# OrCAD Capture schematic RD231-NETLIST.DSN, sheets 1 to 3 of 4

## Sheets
1 4: size A3
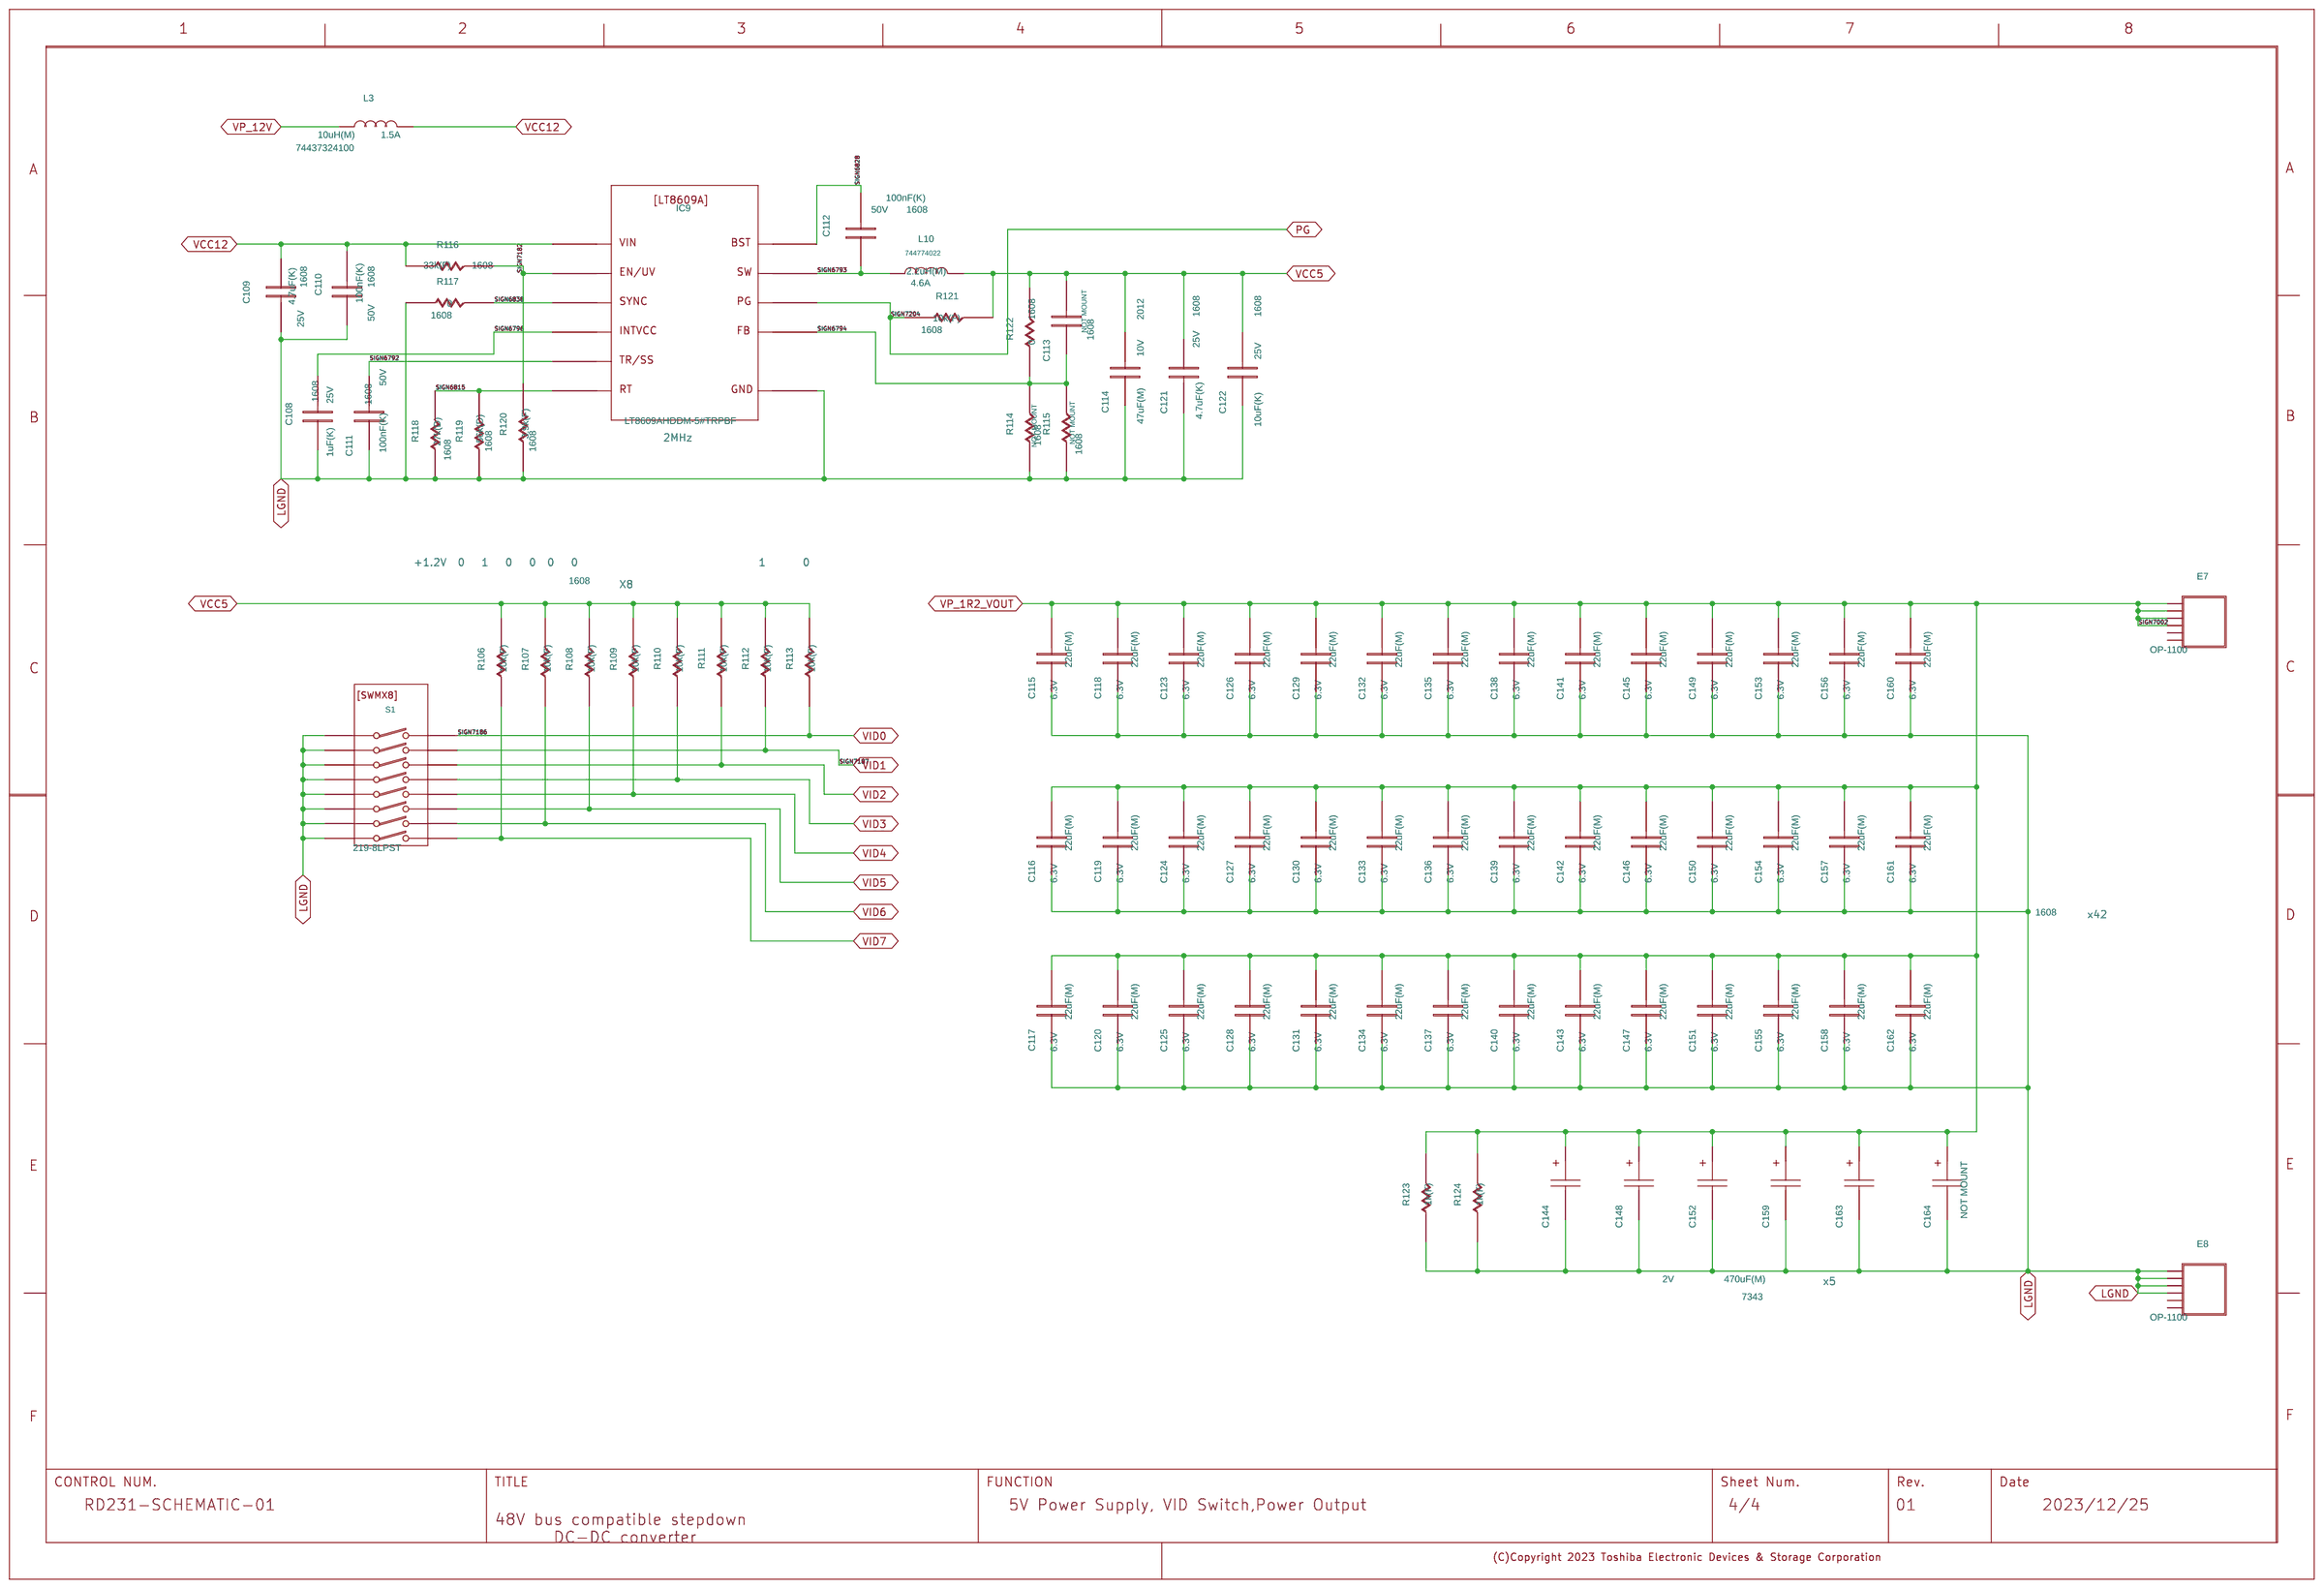
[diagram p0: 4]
2 3: size A3
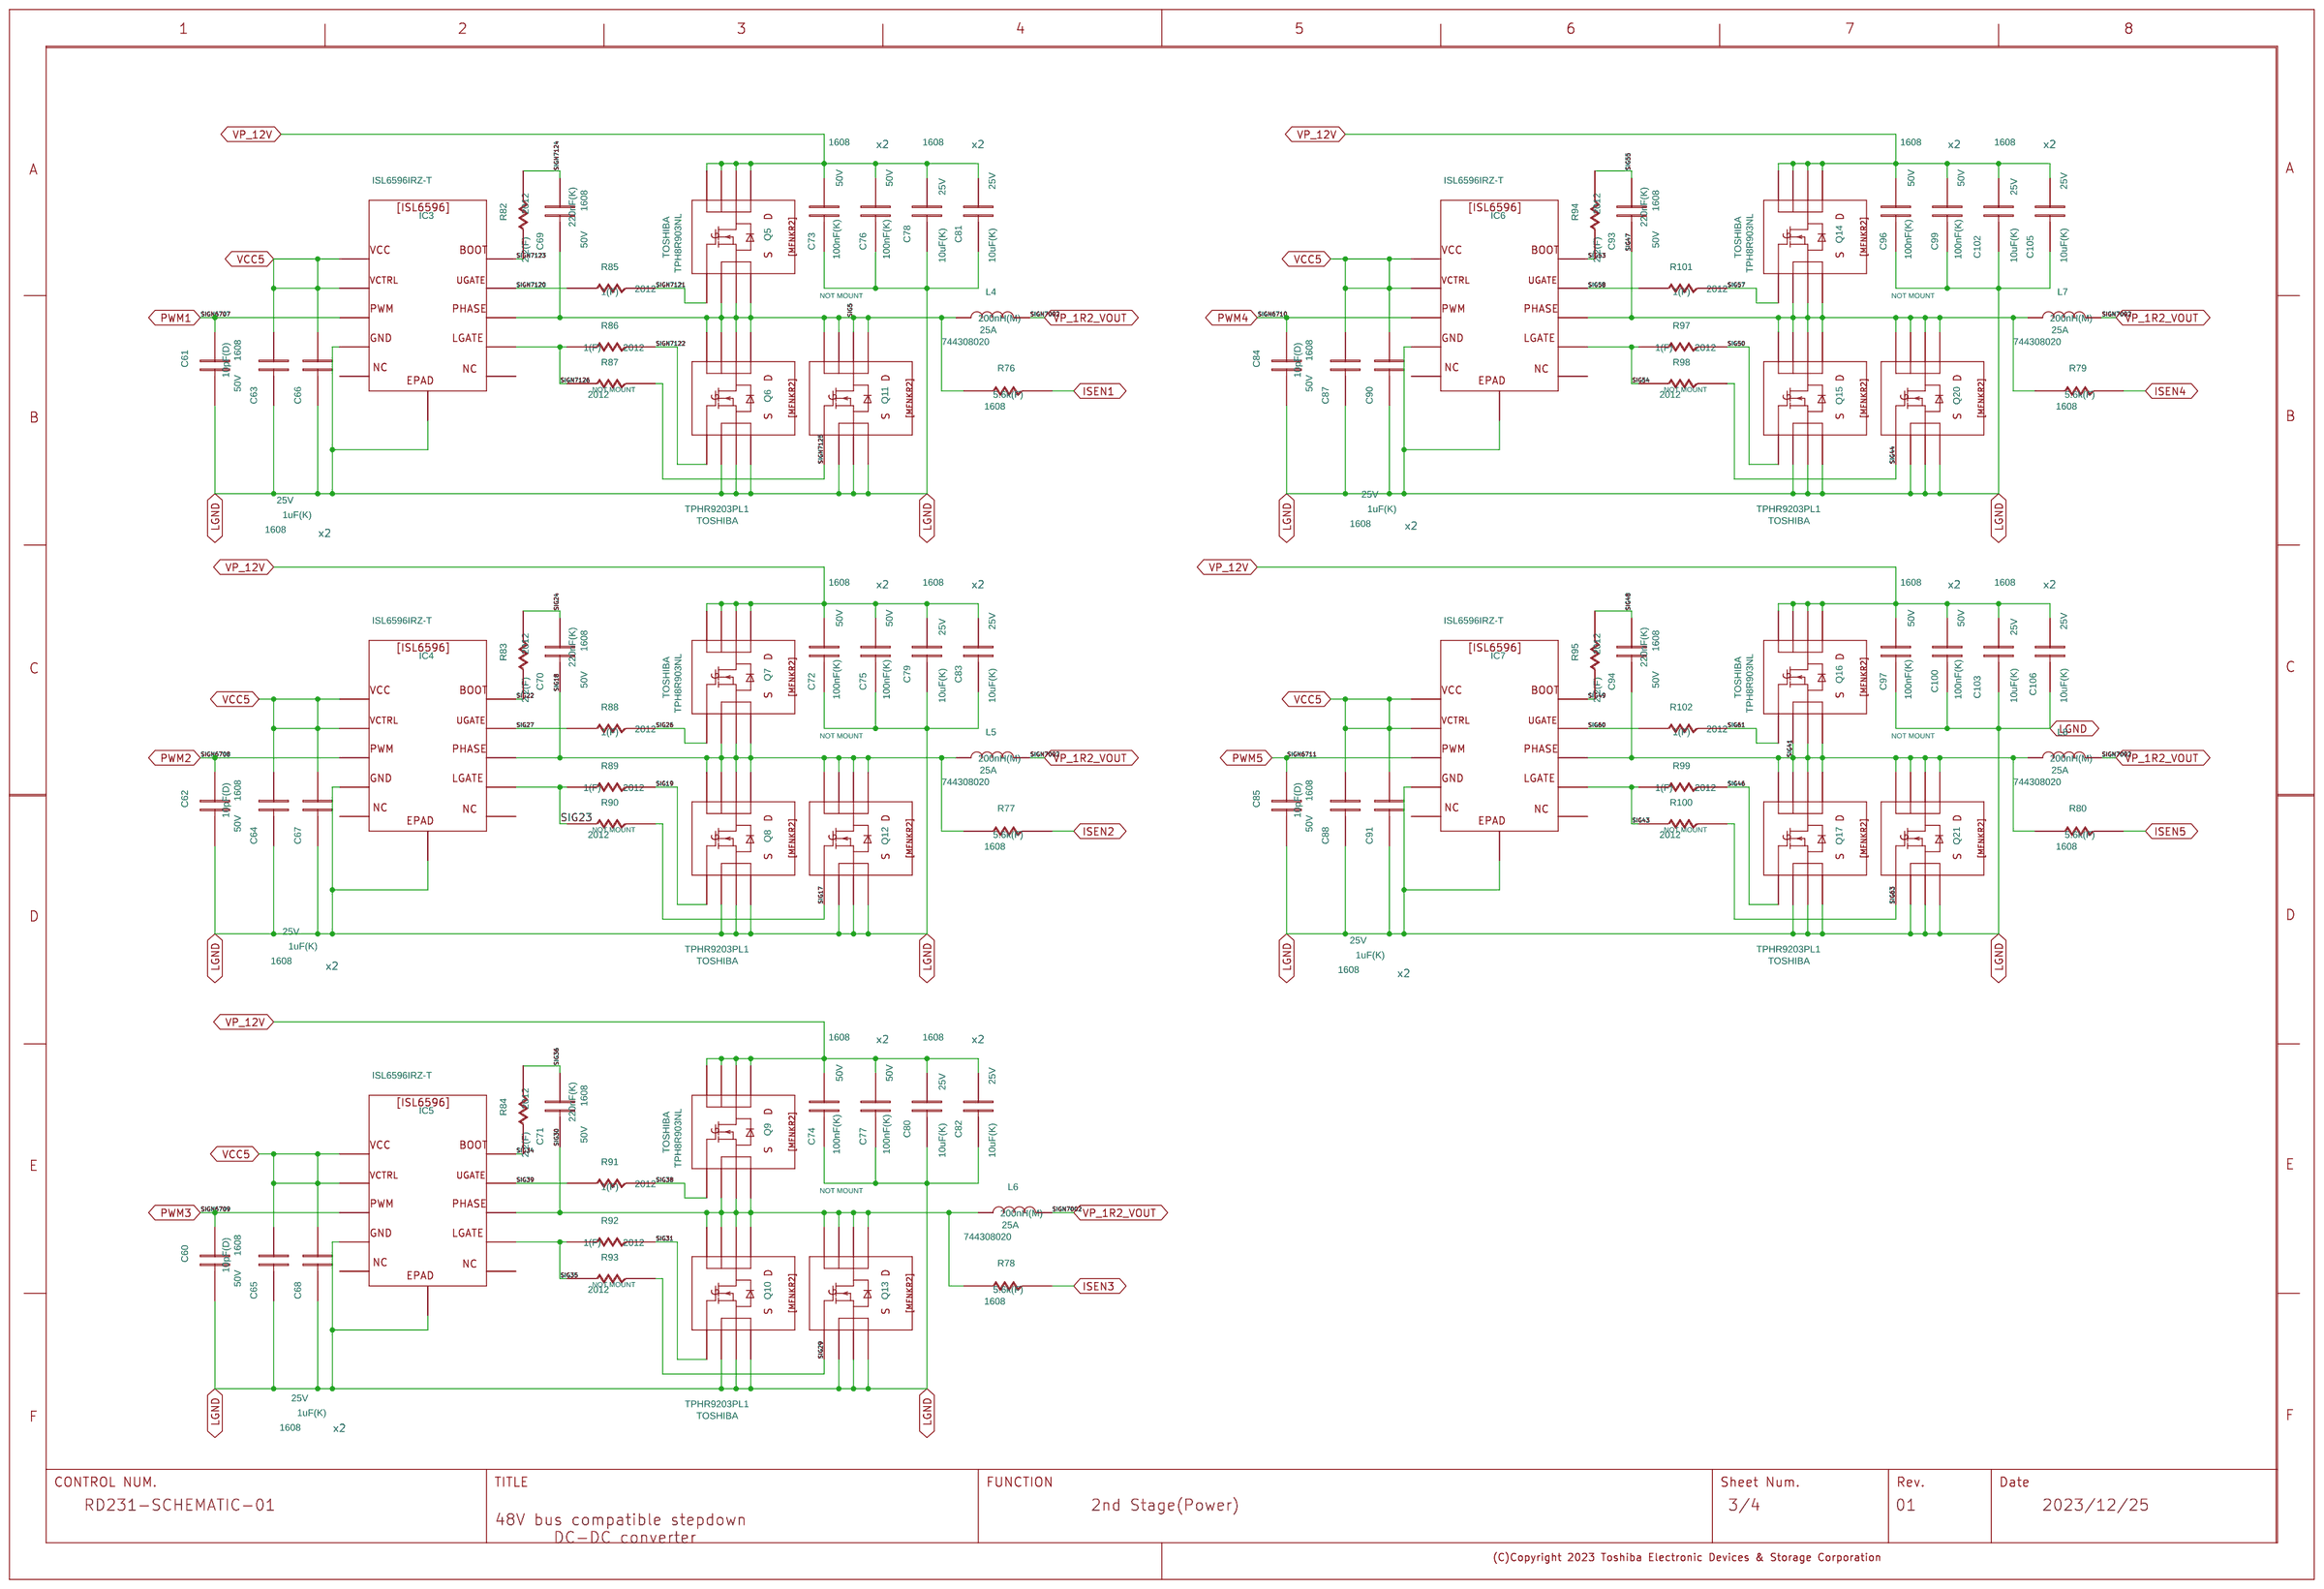
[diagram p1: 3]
3 2: size A3
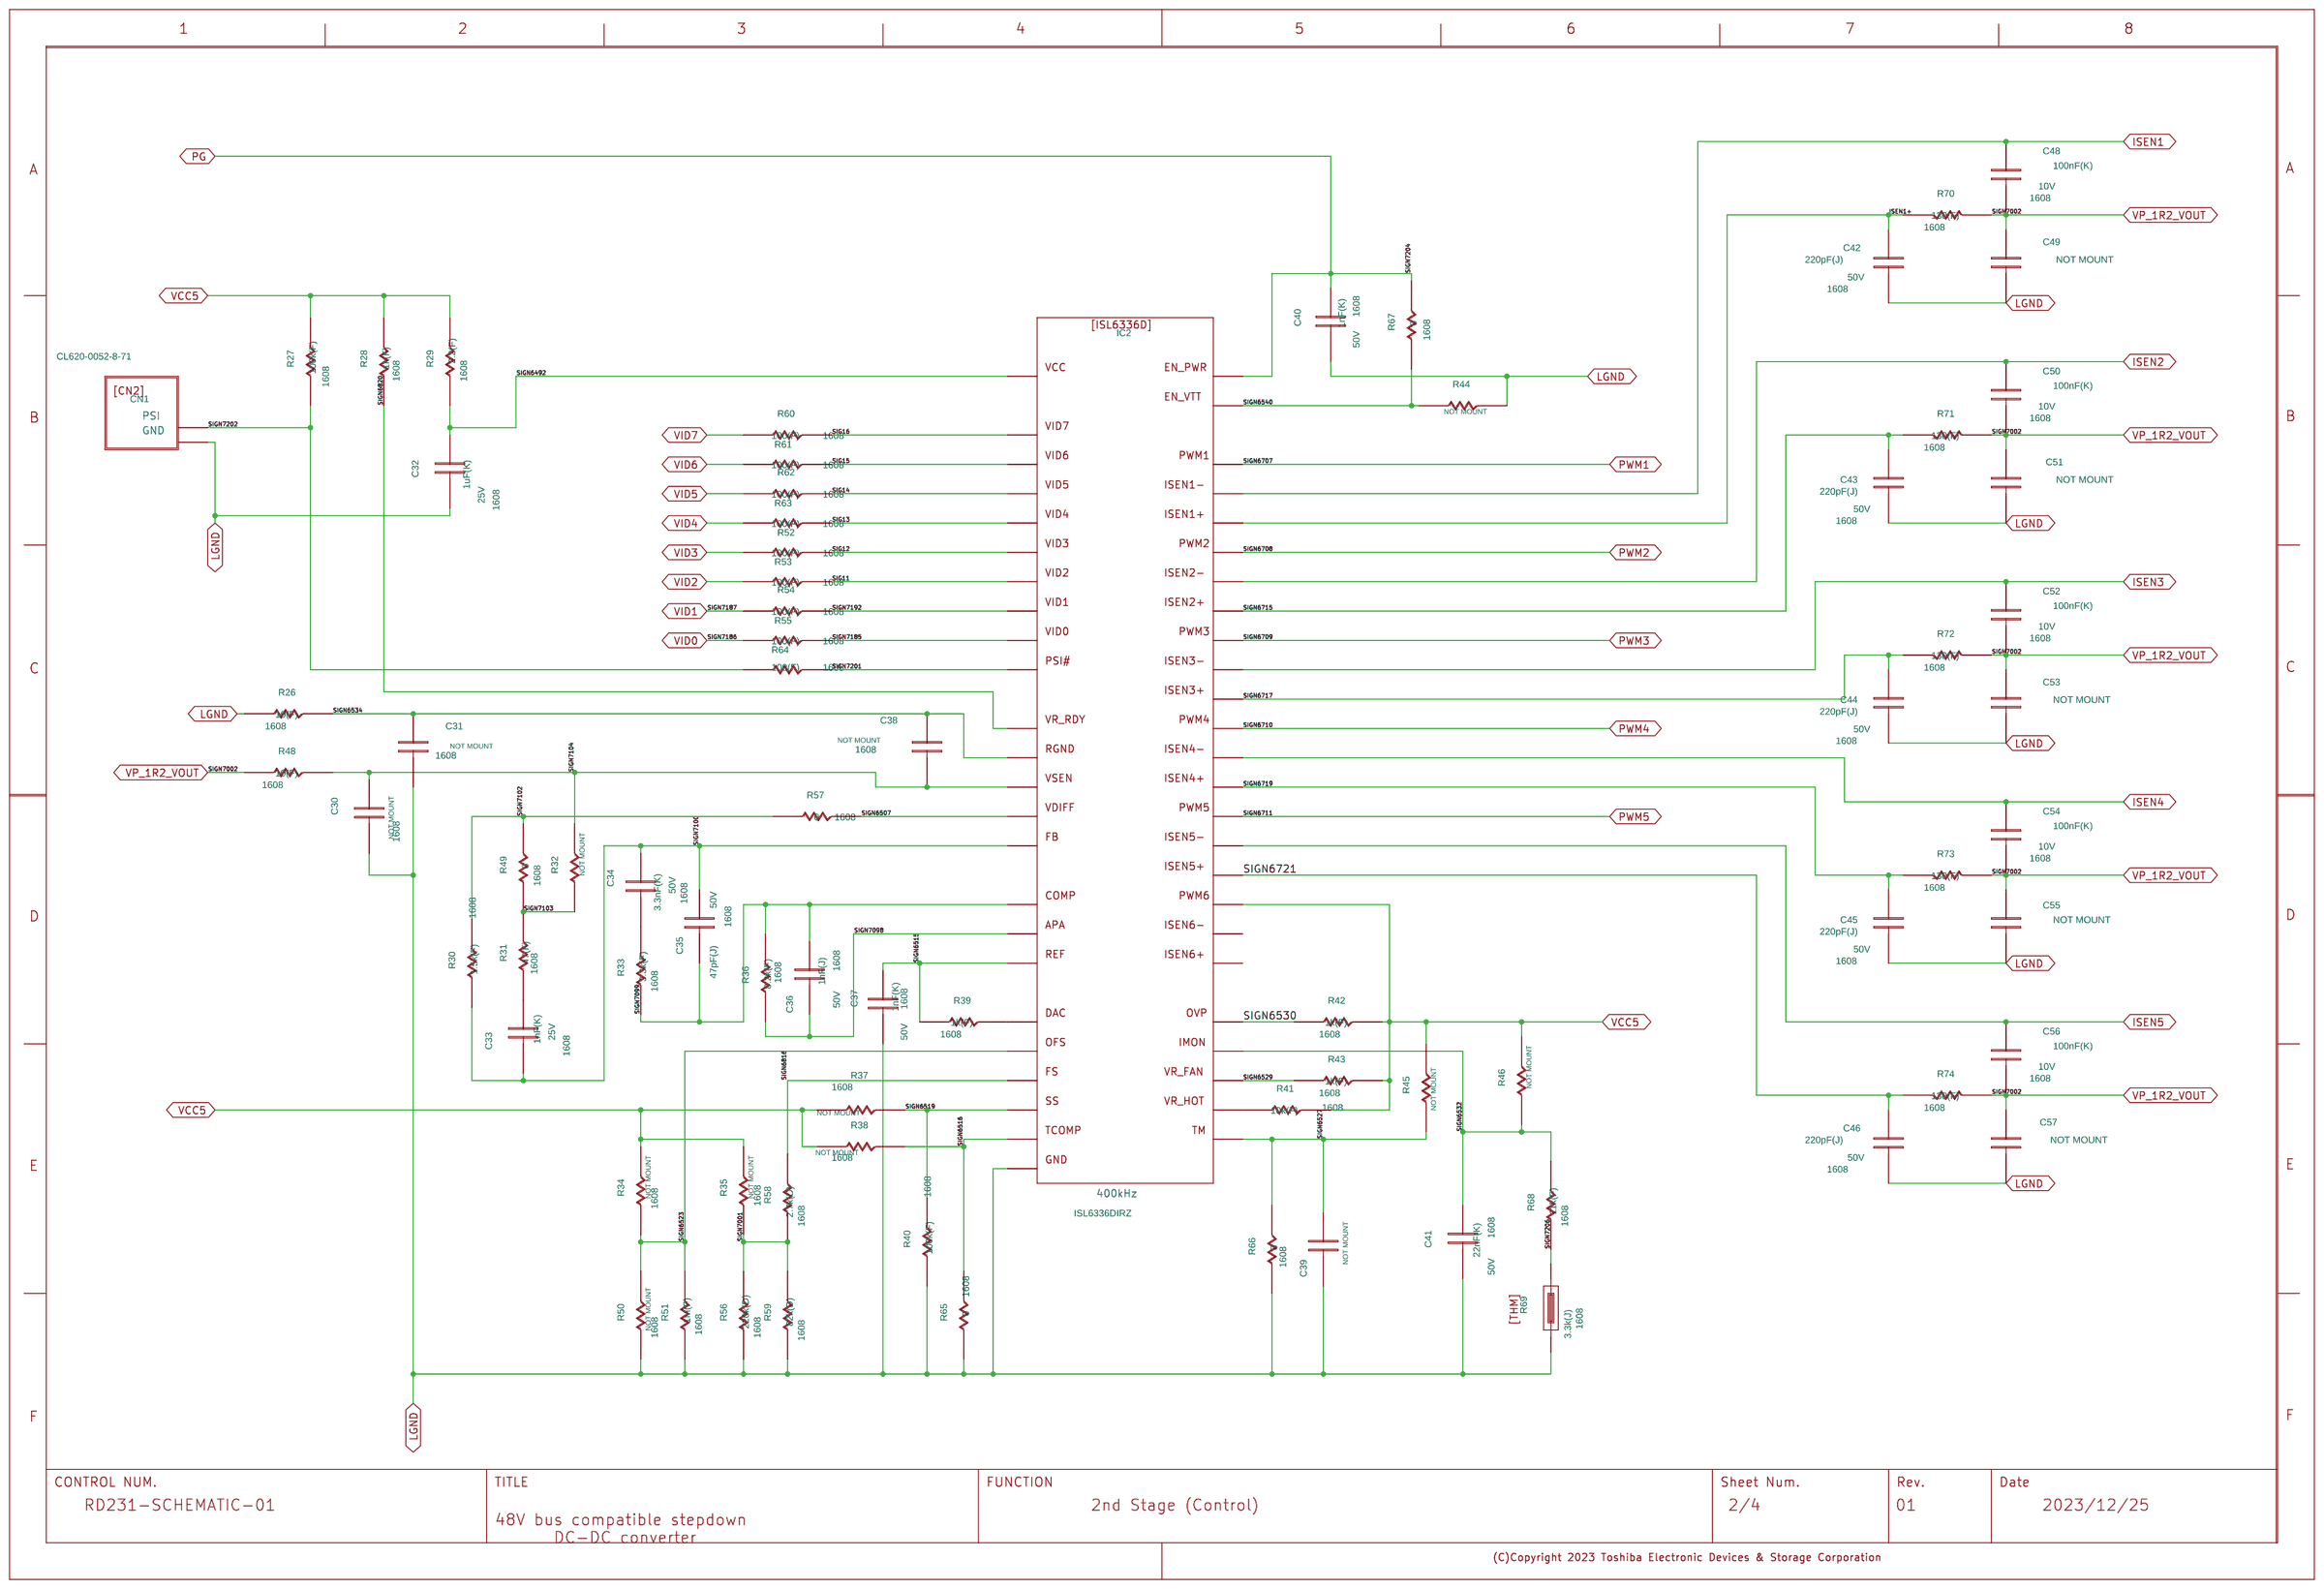
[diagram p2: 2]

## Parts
sheet 2
C30  C
C31  C
C32  C
C33  C
C34  C
C35  C
C36  C
C37  C
C38  C
C39  C
C40  C
C41  C
C42  C
C43  C
C44  C
C45  C
C46  C
C48  C
C49  C
C50  C
C51  C
C52  C
C53  C
C54  C
C55  C
C56  C
C57  C
CN1  CN2
IC2  ISL6336D
R26  R
R27  R
R28  R
R29  R
R30  R
R31  R
R32  R
R33  R
R34  R
R35  R
R36  R
R37  R
R38  R
R39  R
R40  R
R41  R
R42  R
R43  R
R44  R
R45  R
R46  R
R48  R
R49  R
R50  R
R51  R
R52  R
R53  R
R54  R
R55  R
R56  R
R57  R
R58  R
R59  R
R60  R
R61  R
R62  R
R63  R
R64  R
R65  R
R66  R
R67  R
R68  R
R69  THM
R70  R
R71  R
R72  R
R73  R
R74  R
U?#2  WAKU_DEF100
sheet 3
C60  C
C61  C
C62  C
C63  C
C64  C
C65  C
C66  C
C67  C
C68  C
C69  C
C70  C
C71  C
C72  C
C73  C
C74  C
C75  C
C76  C
C77  C
C78  C
C79  C
C80  C
C81  C
C82  C
C83  C
C84  C
C85  C
C87  C
C88  C
C90  C
C91  C
C93  C
C94  C
C96  C
C97  C
C99  C
C100  C
C102  C
C103  C
C105  C
C106  C
IC3  ISL6596
IC4  ISL6596
IC5  ISL6596
IC6  ISL6596
IC7  ISL6596
L4  L
L5  L
L6  L
L7  L
L8  L
Q5  MFNKR2
Q6  MFNKR2
Q7  MFNKR2
Q8  MFNKR2
Q9  MFNKR2
Q10  MFNKR2
Q11  MFNKR2
Q12  MFNKR2
Q13  MFNKR2
Q14  MFNKR2
Q15  MFNKR2
Q16  MFNKR2
Q17  MFNKR2
Q20  MFNKR2
Q21  MFNKR2
R76  R
R77  R
R78  R
R79  R
R80  R
R82  R
R83  R
R84  R
R85  R
R86  R
R87  R
R88  R
R89  R
R90  R
R91  R
R92  R
R93  R
R94  R
R95  R
R97  R
R98  R
R99  R
R100  R
R101  R
R102  R
U?#1  WAKU_DEF100
sheet 4
C108  C
C109  C
C110  C
C111  C
C112  C
C113  C
C114  C
C115  C
C116  C
C117  C
C118  C
C119  C
C120  C
C121  C
C122  C
C123  C
C124  C
C125  C
C126  C
C127  C
C128  C
C129  C
C130  C
C131  C
C132  C
C133  C
C134  C
C135  C
C136  C
C137  C
C138  C
C139  C
C140  C
C141  C
C142  C
C143  C
C144  CP
C145  C
C146  C
C147  C
C148  CP
C149  C
C150  C
C151  C
C152  CP
C153  C
C154  C
C155  C
C156  C
C157  C
C158  C
C159  CP
C160  C
C161  C
C162  C
C163  CP
C164  CP
E7  EB1
E8  EB1
IC9  LT8609A
L3  L
L10  L
R106  R
R107  R
R108  R
R109  R
R110  R
R111  R
R112  R
R113  R
R114  R
R115  R
R116  R
R117  R
R118  R
R119  R
R120  R
R121  R
R122  R
R123  R
R124  R
S1  SWMX8
U?#4  WAKU_DEF100

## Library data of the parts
C30 C31 C38 C39 = C: COMP: G36030011310; COMPONENTNAME: G36030011310_package; COMPONENTTYPE: 4; FNCLASSCODEG: P03-03; FNPARTSNAMEG: CHIP CERAMIC CAPACITOR (1608); FUNCN: G36030011310; GCOUNT: 1; MAXGCOUNT: 1; MFFORMINGDIVP: KC; MFMOUNTSYMBOLP: 80; MFPACKAGEMETHOP: S; MFSOLDERINGPROP: .; NOTMOUNT: NOT MOUNT; PCODE: P03039AAN526; SIZECODESMD: 1608; TOLERANCE: K; USEINPARTSLIST: YES; USEWITHLAYOUT: YES; USEWITHSCHEMA: YES
C32 C63-C68 C87 C88 C90 C91 C108 = C: COMP: G36030011433; COMPONENTNAME: G36030011433_package; COMPONENTTYPE: 4; FNCLASSCODEG: P03-03; FNPARTSNAMEG: CHIP CERAMIC CAPACITOR (1608); FUNCN: G36030011433; GCOUNT: 1; MAXGCOUNT: 1; MFFORMINGDIVP: KC; MFMOUNTSYMBOLP: 80; MFPACKAGEMETHOP: S; MFSOLDERINGPROP: .; PCODE: P03039992230; SIZECODESMD: 1608; USEINPARTSLIST: YES; USEWITHLAYOUT: YES; USEWITHSCHEMA: YES; VAL1: 1uF(K); VAL2: 25V
C33 = C: COMP: G36030011297; COMPONENTNAME: G36030011297_package; COMPONENTTYPE: 4; FNCLASSCODEG: P03-03; FNPARTSNAMEG: CHIP CERAMIC CAPACITOR (1608); FUNCN: G36030011297; GCOUNT: 1; MAXGCOUNT: 1; MFFORMINGDIVP: KC; MFMOUNTSYMBOLP: 80; MFPACKAGEMETHOP: S; MFSOLDERINGPROP: .; PCODE: P03039008221; SIZECODESMD: 1608; TOLERANCE: K; USEINPARTSLIST: YES; USEWITHLAYOUT: YES; USEWITHSCHEMA: YES; VAL1: 1nF(K); VAL2: 25V
C34 = C: COMP: G36030011037; COMPONENTNAME: G36030011037_package; COMPONENTTYPE: 4; FNCLASSCODEG: P03-03; FNPARTSNAMEG: CHIP CERAMIC CAPACITOR (1608); FUNCN: G36030011037; GCOUNT: 1; MAXGCOUNT: 1; MFFORMINGDIVP: KC; MFMOUNTSYMBOLP: 80; MFPACKAGEMETHOP: S; MFSOLDERINGPROP: .; PCODE: P03039A0T125; SIZECODESMD: 1608; TOLERANCE: K; USEINPARTSLIST: YES; USEWITHLAYOUT: YES; USEWITHSCHEMA: YES; VAL1: 3.3nF(K); VAL2: 50V
C35 = C: COMP: G36030011303; COMPONENTNAME: G36030011303_package; COMPONENTTYPE: 4; FNCLASSCODEG: P03-03; FNPARTSNAMEG: CHIP CERAMIC CAPACITOR (1608); FUNCN: G36030011303; GCOUNT: 1; MAXGCOUNT: 1; MFFORMINGDIVP: KC; MFMOUNTSYMBOLP: 80; MFPACKAGEMETHOP: S; MFSOLDERINGPROP: .; PCODE: P03039A0P127; SIZECODESMD: 1608; TOLERANCE: K; USEINPARTSLIST: YES; USEWITHLAYOUT: YES; USEWITHSCHEMA: YES; VAL1: 47pF(J); VAL2: 50V
C36 = C: COMP: G36030011747; COMPONENTNAME: G36030011747_package; COMPONENTTYPE: 4; FNCLASSCODEG: P03-03; FNPARTSNAMEG: CHIP CERAMIC CAPACITOR (1608); FUNCN: G36030011747; GCOUNT: 1; MAXGCOUNT: 1; MFFORMINGDIVP: KC; MFMOUNTSYMBOLP: 80; MFPACKAGEMETHOP: S; MFSOLDERINGPROP: .; PCODE: P03190012112; SIZECODESMD: 1608; USEINPARTSLIST: YES; USEWITHLAYOUT: YES; USEWITHSCHEMA: YES; VAL1: 1nF(J); VAL2: 50V
C37 C40 = C: COMP: G36030011044; COMPONENTNAME: G36030011044_package; COMPONENTTYPE: 4; FNCLASSCODEG: P03-03; FNPARTSNAMEG: CHIP CERAMIC CAPACITOR (1608); FUNCN: G36030011044; GCOUNT: 1; MAXGCOUNT: 1; MFFORMINGDIVP: KC; MFMOUNTSYMBOLP: 80; MFPACKAGEMETHOP: S; MFSOLDERINGPROP: .; PCODE: P03039045226; SIZECODESMD: 1608; TOLERANCE: K; USEINPARTSLIST: YES; USEWITHLAYOUT: YES; USEWITHSCHEMA: YES; VAL1: 1nF(K); VAL2: 50V
C41 = C: COMP: G36030011297; COMPONENTNAME: G36030011297_package; COMPONENTTYPE: 4; FNCLASSCODEG: P03-03; FNPARTSNAMEG: CHIP CERAMIC CAPACITOR (1608); FUNCN: G36030011297; GCOUNT: 1; MAXGCOUNT: 1; MFFORMINGDIVP: KC; MFMOUNTSYMBOLP: 80; MFPACKAGEMETHOP: S; MFSOLDERINGPROP: .; PCODE: P03039008221; SIZECODESMD: 1608; TOLERANCE: K; USEINPARTSLIST: YES; USEWITHLAYOUT: YES; USEWITHSCHEMA: YES; VAL1: 22nF(K); VAL2: 50V
C42-C46 = C: COMP: G36030011488; COMPONENTNAME: G36030011488_package; COMPONENTTYPE: 4; FNCLASSCODEG: P03-03; FNPARTSNAMEG: CHIP CERAMIC CAPACITOR (1608); FUNCN: G36030011488; GCOUNT: 1; MAXGCOUNT: 1; MFFORMINGDIVP: KC; MFMOUNTSYMBOLP: 80; MFPACKAGEMETHOP: S; MFSOLDERINGPROP: .; PCODE: P03039269127; SIZECODESMD: 1608; USEINPARTSLIST: YES; USEWITHLAYOUT: YES; USEWITHSCHEMA: YES; VAL1: 220pF(J); VAL2: 50V
C48 C50 C52 C54 C56 = C: COMP: GDM030000714; COMPONENTNAME: GDM030000714_package; COMPONENTTYPE: 4; FNCLASSCODEG: P03-03; FNPARTSNAMEG: CHIP CERAMIC CAPACITOR (1608); FUNCN: GDM030000714; GCOUNT: 1; MAXGCOUNT: 1; MFFORMINGDIVP: KC; MFMOUNTSYMBOLP: 80; MFPACKAGEMETHOP: S; MFSOLDERINGPROP: .; PCODE: P03039ABE123; SIZECODESMD: 1608; USEINPARTSLIST: YES; USEWITHLAYOUT: YES; USEWITHSCHEMA: YES; VAL1: 100nF(K); VAL2: 10V
C49 C51 C53 C55 C57 = C: COMP: G36030104128; COMPONENTNAME: G36030104128_package; COMPONENTTYPE: 4; FNCLASSCODEG: P03-03; FNPARTSNAMEG: CHIP CERAMIC CAPACITOR (1608); FUNCN: G36030104128; GCOUNT: 1; MAXGCOUNT: 1; MFFORMINGDIVP: KC; MFMOUNTSYMBOLP: 80; MFPACKAGEMETHOP: S; MFSOLDERINGPROP: .; NOTMOUNT: NOT MOUNT; PCODE: P03039ABG127; SIZECODESMD: 1608; USEINPARTSLIST: YES; USEWITHLAYOUT: YES; USEWITHSCHEMA: YES
CN1 = CN2: COMP: ZS_DPJ028; COMPONENTNAME: ZS_DPJ028_package; COMPONENTTYPE: 4; FUNCN: ZS_DPJ028; GCOUNT: 1; MAXGCOUNT: 1; OUMEPARTTYPE: PJ; QUADMODEL: dummymodel; USEINPARTSLIST: YES; USEWITHLAYOUT: YES; USEWITHSCHEMA: YES; VAL1: CL620-0052-8-71; VAL3: CL620-0052-8-71
IC2 = ISL6336D: COMP: ISL6336DIRZ; COMPONENTNAME: ISL6336D.ISL6336D; COMPONENTTYPE: 4; GCOUNT: 1; MAXGCOUNT: 1; OUMEMAKER: Renesas; OUMEMAKERKATAMEI: ISL6336DIRZ; USEINPARTSLIST: YES; USEWITHLAYOUT: YES; USEWITHSCHEMA: YES; VAL1: ISL6336DIRZ; VAL3: ISL6336DIRZ
R26 = R: COMP: G36010104063; COMPONENTNAME: G36010104063_package; COMPONENTTYPE: 4; FNCLASSCODEG: P01-08; FNPARTSNAMEG: CHIP RESISTOR (1608); FUNCN: G36010104063; MFFORMINGDIVP: KC; MFMOUNTSYMBOLP: 80; MFPACKAGEMETHOP: S; MFSOLDERINGPROP: .; NUMBEROFELEMENT: 0; PCODE: P01042036620; SIZECODESMD: 1608; TOLERANCE: F; USEINPARTSLIST: YES; USEWITHLAYOUT: YES; USEWITHSCHEMA: YES; VAL1: 10(F); VAL2: 100mW
R27 R40 = R: COMP: G36010027133; COMPONENTNAME: G36010027133_package; COMPONENTTYPE: 4; FNCLASSCODEG: P01-08; FNPARTSNAMEG: CHIP RESISTOR (1608); FUNCN: G36010027133; MFFORMINGDIVP: KC; MFMOUNTSYMBOLP: 80; MFPACKAGEMETHOP: S; MFSOLDERINGPROP: .; NUMBEROFELEMENT: 0; PCODE: P01042045226; SIZECODESMD: 1608; TOLERANCE: F; USEINPARTSLIST: YES; USEWITHLAYOUT: YES; USEWITHSCHEMA: YES; VAL1: 100k(F); VAL2: 100mW
R28 R123 R124 = R: COMP: G36010027324; COMPONENTNAME: G36010027324_package; COMPONENTTYPE: 4; FNCLASSCODEG: P01-08; FNPARTSNAMEG: CHIP RESISTOR (1608); FUNCN: G36010027324; GCOUNT: 1; MAXGCOUNT: 1; MFFORMINGDIVP: KC; MFMOUNTSYMBOLP: 80; MFPACKAGEMETHOP: S; MFSOLDERINGPROP: .; NUMBEROFELEMENT: 0; PCODE: P01042521225; SIZECODESMD: 1608; TOLERANCE: F; USEINPARTSLIST: YES; USEWITHLAYOUT: YES; USEWITHSCHEMA: YES; VAL1: 1k(F); VAL2: 100mW
R29 = R: COMP: G36010141013; COMPONENTNAME: G36010141013_package; COMPONENTTYPE: 4; FNCLASSCODEG: P01-08; FNPARTSNAMEG: CHIP RESISTOR (1608); FUNCN: G36010141013; MFFORMINGDIVP: KC; MFMOUNTSYMBOLP: 80; MFPACKAGEMETHOP: S; MFSOLDERINGPROP: .; NUMBEROFELEMENT: 0; PCODE: P01183001112; SIZECODESMD: 1608; USEINPARTSLIST: YES; USEWITHLAYOUT: YES; USEWITHSCHEMA: YES; VAL1: 2.2(F); VAL2: 100mW
R30 = R: COMP: G36010104339; COMPONENTNAME: G36010104339_package; COMPONENTTYPE: 4; FNCLASSCODEG: P01-08; FNPARTSNAMEG: CHIP RESISTOR (1608); FUNCN: G36010104339; MFFORMINGDIVP: KC; MFMOUNTSYMBOLP: 80; MFPACKAGEMETHOP: S; MFSOLDERINGPROP: .; NUMBEROFELEMENT: 0; PCODE: P01042159428; SIZECODESMD: 1608; USEINPARTSLIST: YES; USEWITHLAYOUT: YES; USEWITHSCHEMA: YES; VAL1: 1.5k(F); VAL2: 100mW
R31 = R: COMP: K0100346; COMPONENTNAME: K0100346_package; COMPONENTTYPE: 4; FNCLASSCODEG: P01-08; FNPARTSNAMEG: CHIP JUMPER 1608TYPE; FUNCN: K0100346; GCOUNT: 1; MAXGCOUNT: 1; PARTCOMMENT: ã\Z<KC0008> ªtbgvgÉo^³êÄ¢Ü¹ñB; SIZECODESMD: 1608; USEINPARTSLIST: YES; USEWITHLAYOUT: YES; USEWITHSCHEMA: YES; VAL1: 47(F); VAL2: 100mW
R32 R34 R35 R37 R44 = R: COMP: G36010129400; COMPONENTNAME: G36010129400_package; COMPONENTTYPE: 4; FNCLASSCODEG: P01-08; FNPARTSNAMEG: CHIP RESISTOR (1608); FUNCN: G36010129400; MFFORMINGDIVP: KC; MFMOUNTSYMBOLP: 80; MFPACKAGEMETHOP: S; MFSOLDERINGPROP: .; NOTMOUNT: NOT MOUNT; NUMBEROFELEMENT: 0; PCODE: P01117044116; SIZECODESMD: 1608; USEINPARTSLIST: YES; USEWITHLAYOUT: YES; USEWITHSCHEMA: YES
R33 = R: COMP: G36010104353; COMPONENTNAME: G36010104353_package; COMPONENTTYPE: 4; FNCLASSCODEG: P01-08; FNPARTSNAMEG: CHIP RESISTOR (1608); FUNCN: G36010104353; GCOUNT: 1; MAXGCOUNT: 1; MFFORMINGDIVP: KC; MFMOUNTSYMBOLP: 80; MFPACKAGEMETHOP: S; MFSOLDERINGPROP: .; NUMBEROFELEMENT: 0; PCODE: P01042007620; SIZECODESMD: 1608; USEINPARTSLIST: YES; USEWITHLAYOUT: YES; USEWITHSCHEMA: YES; VAL1: 3.3k(F); VAL2: 100mW
R36 = R: COMP: G36010027188; COMPONENTNAME: G36010027188_package; COMPONENTTYPE: 4; FNCLASSCODEG: P01-08; FNPARTSNAMEG: CHIP RESISTOR (1608); FUNCN: G36010027188; MFFORMINGDIVP: KC; MFMOUNTSYMBOLP: 80; MFPACKAGEMETHOP: S; MFSOLDERINGPROP: .; NUMBEROFELEMENT: 0; PCODE: P01042507328; SIZECODESMD: 1608; TOLERANCE: F; USEINPARTSLIST: YES; USEWITHLAYOUT: YES; USEWITHSCHEMA: YES; VAL1: 8.2k(F); VAL2: 100mW
R38 = R: COMP: G36010027034; COMPONENTNAME: G36010027034_package; COMPONENTTYPE: 4; FNCLASSCODEG: P01-08; FNPARTSNAMEG: CHIP RESISTOR (1608); FUNCN: G36010027034; MFFORMINGDIVP: KC; MFMOUNTSYMBOLP: 80; MFPACKAGEMETHOP: S; MFSOLDERINGPROP: .; NOTMOUNT: NOT MOUNT; NUMBEROFELEMENT: 0; PCODE: P01042049A26; SIZECODESMD: 1608; TOLERANCE: F; USEINPARTSLIST: YES; USEWITHLAYOUT: YES; USEWITHSCHEMA: YES
R39 R42 R43 = R: COMP: G36010027324; COMPONENTNAME: G36010027324_package; COMPONENTTYPE: 4; FNCLASSCODEG: P01-08; FNPARTSNAMEG: CHIP RESISTOR (1608); FUNCN: G36010027324; MFFORMINGDIVP: KC; MFMOUNTSYMBOLP: 80; MFPACKAGEMETHOP: S; MFSOLDERINGPROP: .; NUMBEROFELEMENT: 0; PCODE: P01042521225; SIZECODESMD: 1608; TOLERANCE: F; USEINPARTSLIST: YES; USEWITHLAYOUT: YES; USEWITHSCHEMA: YES; VAL1: 1k(F); VAL2: 100mW
R41 R106-R113 = R: COMP: G36010027034; COMPONENTNAME: G36010027034_package; COMPONENTTYPE: 4; FNCLASSCODEG: P01-08; FNPARTSNAMEG: CHIP RESISTOR (1608); FUNCN: G36010027034; MFFORMINGDIVP: KC; MFMOUNTSYMBOLP: 80; MFPACKAGEMETHOP: S; MFSOLDERINGPROP: .; NUMBEROFELEMENT: 0; PCODE: P01042049A26; SIZECODESMD: 1608; TOLERANCE: F; USEINPARTSLIST: YES; USEWITHLAYOUT: YES; USEWITHSCHEMA: YES; VAL1: 10k(F); VAL2: 100mW
R45 = R: COMP: G36010027324; COMPONENTNAME: G36010027324_package; COMPONENTTYPE: 4; FNCLASSCODEG: P01-08; FNPARTSNAMEG: CHIP RESISTOR (1608); FUNCN: G36010027324; MFFORMINGDIVP: KC; MFMOUNTSYMBOLP: 80; MFPACKAGEMETHOP: S; MFSOLDERINGPROP: .; NOTMOUNT: NOT MOUNT; NUMBEROFELEMENT: 0; PCODE: P01042521225; SIZECODESMD: 1608; TOLERANCE: F; USEINPARTSLIST: YES; USEWITHLAYOUT: YES; USEWITHSCHEMA: YES
R46 = R: COMP: G5101106E109; COMPONENTNAME: G5101106E109_package; COMPONENTTYPE: 4; FNCLASSCODEG: P01-08; FNPARTSNAMEG: CHIP RESISTOR (1608); FUNCN: G5101106E109; MFFORMINGDIVP: KC; MFMOUNTSYMBOLP: 80; MFPACKAGEMETHOP: S; MFSOLDERINGPROP: .; NOTMOUNT: NOT MOUNT; NUMBEROFELEMENT: 0; PCODE: P01042153228; SIZECODESMD: 1608; USEINPARTSLIST: YES; USEWITHLAYOUT: YES; USEWITHSCHEMA: YES
R48 = R: COMP: G36010104063; COMPONENTNAME: G36010104063_package; COMPONENTTYPE: 4; FNCLASSCODEG: P01-08; FNPARTSNAMEG: CHIP RESISTOR (1608); FUNCN: G36010104063; GCOUNT: 1; MAXGCOUNT: 1; MFFORMINGDIVP: KC; MFMOUNTSYMBOLP: 80; MFPACKAGEMETHOP: S; MFSOLDERINGPROP: .; NUMBEROFELEMENT: 0; PCODE: P01042036620; SIZECODESMD: 1608; TOLERANCE: F; USEINPARTSLIST: YES; USEWITHLAYOUT: YES; USEWITHSCHEMA: YES; VAL1: 10(F); VAL2: 100mW
R49 R57 R65-R67 R117 R122 = R: COMP: K0100346; COMPONENTNAME: K0100346_package; COMPONENTTYPE: 4; FNCLASSCODEG: P01-08; FNPARTSNAMEG: CHIP JUMPER 1608TYPE; FUNCN: K0100346; GCOUNT: 1; MAXGCOUNT: 1; PARTCOMMENT: ã\Z<KC0008> ªtbgvgÉo^³êÄ¢Ü¹ñB; SIZECODESMD: 1608; USEINPARTSLIST: YES; USEWITHLAYOUT: YES; USEWITHSCHEMA: YES; VAL1: 0
R50 = R: COMP: G36010129639; COMPONENTNAME: G36010129639_package; COMPONENTTYPE: 4; FNCLASSCODEG: P01-08; FNPARTSNAMEG: CHIP RESISTOR (1608); FUNCN: G36010129639; GCOUNT: 1; MAXGCOUNT: 1; MFFORMINGDIVP: KC; MFMOUNTSYMBOLP: 80; MFPACKAGEMETHOP: S; MFSOLDERINGPROP: .; NOTMOUNT: NOT MOUNT; NUMBEROFELEMENT: 0; PCODE: P01117067115; SIZECODESMD: 1608; USEINPARTSLIST: YES; USEWITHLAYOUT: YES; USEWITHSCHEMA: YES
R51 = R: COMP: G5101106E109; COMPONENTNAME: G5101106E109_package; COMPONENTTYPE: 4; FNCLASSCODEG: P01-08; FNPARTSNAMEG: CHIP RESISTOR (1608); FUNCN: G5101106E109; GCOUNT: 1; MAXGCOUNT: 1; MFFORMINGDIVP: KC; MFMOUNTSYMBOLP: 80; MFPACKAGEMETHOP: S; MFSOLDERINGPROP: .; NUMBEROFELEMENT: 0; PCODE: P01042153228; SIZECODESMD: 1608; USEINPARTSLIST: YES; USEWITHLAYOUT: YES; USEWITHSCHEMA: YES; VAL1: 1M(F); VAL2: 100mW
R52-R55 R60-R64 = R: COMP: G36010104087; COMPONENTNAME: G36010104087_package; COMPONENTTYPE: 4; FNCLASSCODEG: P01-08; FNPARTSNAMEG: CHIP RESISTOR (1608); FUNCN: G36010104087; GCOUNT: 1; MAXGCOUNT: 1; MFFORMINGDIVP: KC; MFMOUNTSYMBOLP: 80; MFPACKAGEMETHOP: S; MFSOLDERINGPROP: .; NUMBEROFELEMENT: 0; PCODE: P01042041426; SIZECODESMD: 1608; TOLERANCE: F; USEINPARTSLIST: YES; USEWITHLAYOUT: YES; USEWITHSCHEMA: YES; VAL1: 100(F); VAL2: 100mW
R56 = R: COMP: G36010014355; COMPONENTNAME: G36010014355_package; COMPONENTTYPE: 4; FNCLASSCODEG: P01-08; FNPARTSNAMEG: CHIP RESISTOR (1608); FUNCN: G36010014355; GCOUNT: 1; MAXGCOUNT: 1; MFFORMINGDIVP: KC; MFMOUNTSYMBOLP: 80; MFPACKAGEMETHOP: S; MFSOLDERINGPROP: .; NUMBEROFELEMENT: 0; PCODE: P01042201820; SIZECODESMD: 1608; USEINPARTSLIST: YES; USEWITHLAYOUT: YES; USEWITHSCHEMA: YES; VAL1: 220k(D); VAL2: 62.5mW
R58 = R: COMP: G36010129356; COMPONENTNAME: G36010129356_package; COMPONENTTYPE: 4; FNCLASSCODEG: P01-08; FNPARTSNAMEG: CHIP RESISTOR (1608); FUNCN: G36010129356; GCOUNT: 1; MAXGCOUNT: 1; MFFORMINGDIVP: KC; MFMOUNTSYMBOLP: 80; MFPACKAGEMETHOP: S; MFSOLDERINGPROP: .; NUMBEROFELEMENT: 0; PCODE: P01117039112; SIZECODESMD: 1608; USEINPARTSLIST: YES; USEWITHLAYOUT: YES; USEWITHSCHEMA: YES; VAL1: 2.7k(D); VAL2: 62.5mW
R59 = R: COMP: G36010129714; COMPONENTNAME: G36010129714_package; COMPONENTTYPE: 4; FNCLASSCODEG: P01-08; FNPARTSNAMEG: CHIP RESISTOR (1608); FUNCN: G36010129714; GCOUNT: 1; MAXGCOUNT: 1; MFFORMINGDIVP: KC; MFMOUNTSYMBOLP: 80; MFPACKAGEMETHOP: S; MFSOLDERINGPROP: .; NUMBEROFELEMENT: 0; PCODE: P01117075110; SIZECODESMD: 1608; USEINPARTSLIST: YES; USEWITHLAYOUT: YES; USEWITHSCHEMA: YES; VAL1: 82k(D); VAL2: 62.5mW
R68 = R: COMP: G36010027164; COMPONENTNAME: G36010027164_package; COMPONENTTYPE: 4; FNCLASSCODEG: P01-08; FNPARTSNAMEG: CHIP RESISTOR (1608); FUNCN: G36010027164; GCOUNT: 1; MAXGCOUNT: 1; MFFORMINGDIVP: KC; MFMOUNTSYMBOLP: 80; MFPACKAGEMETHOP: S; MFSOLDERINGPROP: .; NUMBEROFELEMENT: 0; PCODE: P01042066221; SIZECODESMD: 1608; TOLERANCE: F; USEINPARTSLIST: YES; USEWITHLAYOUT: YES; USEWITHSCHEMA: YES; VAL1: 11k(F); VAL2: 100mW
R69 = THM: COMP: K0900027; COMPONENTKIND: 105; COMPONENTNAME: K0900027_package; COMPONENTTYPE: 4; DCSPARKOVERVOLT: 0.000000000000000; FNCLASSCODEG: P09-01; FNPARTSCODEG: MT; FNPARTSNAMEG: CHIP NTC THERMISTOR; FUNCN: K0900027; GCOUNT: 1; MAXGCOUNT: 1; MFFORMINGDIVP: KC; MFMOUNTSYMBOLP: 80; MFPACKAGEMETHOP: S; MFSOLDERINGPROP: .; OUMEPARTTYPE: MT; PARTCOMMENT: ã\Z<KC0008> ªtbgvgÉo^³êÄ¢Ü¹ñB; SIZECODESMD: 1608; USEINPARTSLIST: YES; USEWITHLAYOUT: YES; USEWITHSCHEMA: YES; VAL1: 3.3k(J); VAL2: 100mW; VARISTORVOLTAGE: 0
R70-R74 = R: COMP: G5101104N107; COMPONENTNAME: G5101104N107_package; COMPONENTTYPE: 4; FNCLASSCODEG: P01-08; FNPARTSNAMEG: CHIP RESISTOR (1608); FUNCN: G5101104N107; GCOUNT: 1; MAXGCOUNT: 1; MFFORMINGDIVP: KC; MFMOUNTSYMBOLP: 80; MFPACKAGEMETHOP: S; MFSOLDERINGPROP: .; NUMBEROFELEMENT: 0; PCODE: P01042089220; SIZECODESMD: 1608; USEINPARTSLIST: YES; USEWITHLAYOUT: YES; USEWITHSCHEMA: YES; VAL1: 130(F); VAL2: 100mW
U?#2 = WAKU_DEF100: AUTHOR: d9000436; COMPONENTTYPE: 2; DATE: 2023/12/25; DRAWINGNUMBER: RD231-SCHEMATIC-01; FUNCTION: 2nd Stage (Control); REVISION: 01; SAVEAREA0: -56280,0,471144,298016; SHEETNUMBER: 2/4; TIME: 20:22:11; TITLE: 48V bus compatible stepdown / DC-DC converter; UPDATEDATE: 2024/01/12; UPDATETIME: 11:35:27; UPDATEUSER: sptcae13
C60-C62 C84 C85 = C: COMP: G36030011013; COMPONENTNAME: G36030011013_package; COMPONENTTYPE: 4; FNCLASSCODEG: P03-03; FNPARTSNAMEG: CHIP CERAMIC CAPACITOR (1608); FUNCN: G36030011013; GCOUNT: 1; MAXGCOUNT: 1; MFFORMINGDIVP: KC; MFMOUNTSYMBOLP: 80; MFPACKAGEMETHOP: S; MFSOLDERINGPROP: .; PCODE: P03039185229; SIZECODESMD: 1608; TOLERANCE: D; USEINPARTSLIST: YES; USEWITHLAYOUT: YES; USEWITHSCHEMA: YES; VAL1: 10pF(D); VAL2: 50V
C69-C71 C93 C94 = C: COMP: G36030104104; COMPONENTNAME: G36030104104_package; COMPONENTTYPE: 4; FNCLASSCODEG: P03-03; FNPARTSNAMEG: CHIP CERAMIC CAPACITOR (1608); FUNCN: G36030104104; GCOUNT: 1; MAXGCOUNT: 1; MFFORMINGDIVP: KC; MFMOUNTSYMBOLP: 80; MFPACKAGEMETHOP: S; MFSOLDERINGPROP: .; PCODE: P03039ABE123; SIZECODESMD: 1608; USEINPARTSLIST: YES; USEWITHLAYOUT: YES; USEWITHSCHEMA: YES; VAL1: 220nF(K); VAL2: 50V
C72-C77 C96 C97 C99 C100 = C: COMP: G36030011419; COMPONENTNAME: G36030011419_package; COMPONENTTYPE: 4; FNCLASSCODEG: P03-03; FNPARTSNAMEG: CHIP CERAMIC CAPACITOR (1608); FUNCN: G36030011419; GCOUNT: 1; MAXGCOUNT: 1; MFFORMINGDIVP: KC; MFMOUNTSYMBOLP: 80; MFPACKAGEMETHOP: S; MFSOLDERINGPROP: .; PCODE: P03039996139; SIZECODESMD: 1608; USEINPARTSLIST: YES; USEWITHLAYOUT: YES; USEWITHSCHEMA: YES; VAL1: 100nF(K); VAL2: 50V
C78-C83 C102 C103 C105 C106 = C: COMP: G36030011433; COMPONENTNAME: G36030011433_package; COMPONENTTYPE: 4; FNCLASSCODEG: P03-03; FNPARTSNAMEG: CHIP CERAMIC CAPACITOR (1608); FUNCN: G36030011433; GCOUNT: 1; MAXGCOUNT: 1; MFFORMINGDIVP: KC; MFMOUNTSYMBOLP: 80; MFPACKAGEMETHOP: S; MFSOLDERINGPROP: .; PCODE: P03039992230; SIZECODESMD: 1608; USEINPARTSLIST: YES; USEWITHLAYOUT: YES; USEWITHSCHEMA: YES; VAL1: 10uF(K); VAL2: 25V
IC3-IC7 = ISL6596: COMP: G36470287016; COMPONENTTYPE: 4; VAL1: ISL6596IRZ-T; VAL3: ISL6596IRZ-T
L4-L8 = L: COMP: 7443082022; COMPONENTNAME: pinass:L_func:L; COMPONENTTYPE: 8; GCOUNT: 1; MAXGCOUNT: 1; OUMEMAKER: Wurth; OUMEMAKERKATAMEI: 7443082022; USEINPARTSLIST: YES; USEWITHLAYOUT: YES; USEWITHSCHEMA: YES; VAL1: 200nH(M); VAL2: 25A; VAL3: 744308020
Q5 Q7 Q9 Q14 Q16 = MFNKR2: COMP: TPH6R003NL; COMPONENTNAME: MFNKR2_MFNKR2; COMPONENTTYPE: 4; GCOUNT: 1; MAXGCOUNT: 1; OUMEMAKER: TOSHIBA; OUMEMAKERKATAMEI: TPH6R003NL; USEINPARTSLIST: YES; USERCOMPTEXT3: TOSHIBA; USEWITHLAYOUT: YES; USEWITHSCHEMA: YES; VAL1: TPH8R903NL; VAL3: TPH8R903NL
Q6 Q8 Q10 Q15 Q17 = MFNKR2: COMP: TPH6R003NL; COMPONENTNAME: MFNKR2_MFNKR2; COMPONENTTYPE: 4; GCOUNT: 1; MAXGCOUNT: 1; OUMEMAKER: TOSHIBA; OUMEMAKERKATAMEI: TPH6R003NL; USEINPARTSLIST: YES; USERCOMPTEXT3: TOSHIBA; USEWITHLAYOUT: YES; USEWITHSCHEMA: YES; VAL1: TPHR9203PL1; VAL3: TPHR9203PL1
Q11-Q13 Q20 Q21 = MFNKR2: COMP: TPH6R003NL; COMPONENTNAME: MFNKR2_MFNKR2; COMPONENTTYPE: 4; GCOUNT: 1; MAXGCOUNT: 1; NOTMOUNT: NOT MOUNT; OUMEMAKER: TOSHIBA; OUMEMAKERKATAMEI: TPH6R003NL; USEINPARTSLIST: YES; USEWITHLAYOUT: YES; USEWITHSCHEMA: YES
R76-R80 = R: COMPONENTTYPE: 4; SIZECODESMD: 1608; VAL1: 5.6k(F); VAL2: 62.5mW
R82-R84 R94 R95 = R: COMP: G36010106012; COMPONENTNAME: G36010106012_package; COMPONENTTYPE: 4; FNCLASSCODEG: P01-08; FNPARTSNAMEG: CHIP RESISTOR (2012); FUNCN: G36010106012; GCOUNT: 1; MAXGCOUNT: 1; MFFORMINGDIVP: KC; MFMOUNTSYMBOLP: 90; MFPACKAGEMETHOP: S; MFSOLDERINGPROP: .; NUMBEROFELEMENT: 0; PCODE: P01048019214; SIZECODESMD: 2012; USEINPARTSLIST: YES; USEWITHLAYOUT: YES; USEWITHSCHEMA: YES; VAL1: 2.2(F); VAL2: 125mW
R85 R86 R88 R89 R91 R92 R97 R99 R101 R102 = R: COMP: G36010106081; COMPONENTNAME: G36010106081_package; COMPONENTTYPE: 4; FNCLASSCODEG: P01-08; FNPARTSNAMEG: CHIP RESISTOR (2012); FUNCN: G36010106081; GCOUNT: 1; MAXGCOUNT: 1; MFFORMINGDIVP: KC; MFMOUNTSYMBOLP: 90; MFPACKAGEMETHOP: S; MFSOLDERINGPROP: .; NUMBEROFELEMENT: 0; PCODE: P01048017210; SIZECODESMD: 2012; USEINPARTSLIST: YES; USEWITHLAYOUT: YES; USEWITHSCHEMA: YES; VAL1: 1(F); VAL2: 125mW
R87 R90 R93 R98 R100 = R: COMP: G36010106081; COMPONENTNAME: G36010106081_package; COMPONENTTYPE: 4; FNCLASSCODEG: P01-08; FNPARTSNAMEG: CHIP RESISTOR (2012); FUNCN: G36010106081; GCOUNT: 1; MAXGCOUNT: 1; MFFORMINGDIVP: KC; MFMOUNTSYMBOLP: 90; MFPACKAGEMETHOP: S; MFSOLDERINGPROP: .; NOTMOUNT: NOT MOUNT; NUMBEROFELEMENT: 0; PCODE: P01048017210; SIZECODESMD: 2012; USEINPARTSLIST: YES; USEWITHLAYOUT: YES; USEWITHSCHEMA: YES
U?#1 = WAKU_DEF100: AUTHOR: osozawa; COMPONENTTYPE: 2; DATE: 2023/12/25; DRAWINGNUMBER: RD231-SCHEMATIC-01; FUNCTION: 2nd Stage(Power); REVISION: 01; SAVEAREA0: 315434,-7824,400773,39368; SHEETNUMBER: 3/4; TIME: 14:26:19; TITLE: 48V bus compatible stepdown / DC-DC converter; UPDATEDATE: 2024/01/12; UPDATETIME: 11:36:35; UPDATEUSER: sptcae13
C109 = C: COMP: GDM030000053; COMPONENTNAME: GDM030000053_package; COMPONENTTYPE: 4; FNCLASSCODEG: P03-03; FNPARTSNAMEG: CHIP CERAMIC CAPACITOR (1608); FUNCN: GDM030000053; GCOUNT: 1; MAXGCOUNT: 1; MFFORMINGDIVP: KC; MFMOUNTSYMBOLP: 80; MFPACKAGEMETHOP: S; MFSOLDERINGPROP: .; PCODE: P03B000000MS; SIZECODESMD: 1608; USEINPARTSLIST: YES; USEWITHLAYOUT: YES; USEWITHSCHEMA: YES; VAL1: 4.7uF(K); VAL2: 25V
C110 C112 = C: COMP: G36030104036; COMPONENTNAME: G36030104036_package; COMPONENTTYPE: 4; FNCLASSCODEG: P03-03; FNPARTSNAMEG: CHIP CERAMIC CAPACITOR (1608); FUNCN: G36030104036; GCOUNT: 1; MAXGCOUNT: 1; MFFORMINGDIVP: KC; MFMOUNTSYMBOLP: 80; MFPACKAGEMETHOP: S; MFSOLDERINGPROP: .; PCODE: P03039A6F224; SIZECODESMD: 1608; USEINPARTSLIST: YES; USEWITHLAYOUT: YES; USEWITHSCHEMA: YES; VAL1: 100nF(K); VAL2: 50V
C111 = C: COMP: GDM030001137; COMPONENTNAME: GDM030001137_package; COMPONENTTYPE: 4; FNCLASSCODEG: P03-03; FNPARTSNAMEG: CHIP CERAMIC CAPACITOR (1608); FUNCN: GDM030001137; GCOUNT: 1; MAXGCOUNT: 1; MFFORMINGDIVP: KC; MFMOUNTSYMBOLP: 80; MFPACKAGEMETHOP: S; MFSOLDERINGPROP: .; PARTCOMMENT: ã\Z<KC0008> ªtbgvgÉo^³êÄ¢Ü¹ñB; PCODE: P03B000001KW; SIZECODESMD: 1608; USEINPARTSLIST: YES; USEWITHLAYOUT: YES; USEWITHSCHEMA: YES; VAL1: 100nF(K); VAL2: 50V
C113 = C: COMP: G36030011013; COMPONENTNAME: G36030011013_package; COMPONENTTYPE: 4; FNCLASSCODEG: P03-03; FNPARTSNAMEG: CHIP CERAMIC CAPACITOR (1608); FUNCN: G36030011013; GCOUNT: 1; MAXGCOUNT: 1; MFFORMINGDIVP: KC; MFMOUNTSYMBOLP: 80; MFPACKAGEMETHOP: S; MFSOLDERINGPROP: .; NOTMOUNT: NOT MOUNT; PCODE: P03039185229; SIZECODESMD: 1608; TOLERANCE: D; USEINPARTSLIST: YES; USEWITHLAYOUT: YES; USEWITHSCHEMA: YES
C114 = C: COMP: GDM030000019; COMPONENTNAME: GDM030000019_package; COMPONENTTYPE: 4; FNCLASSCODEG: P03-03; FNPARTSNAMEG: CHIP CERAMIC CAPACITOR (2012); FUNCN: GDM030000019; GCOUNT: 1; MAXGCOUNT: 1; MFFORMINGDIVP: KC; MFMOUNTSYMBOLP: 80; MFPACKAGEMETHOP: S; MFSOLDERINGPROP: .; PCODE: P03B0000004U; SIZECODESMD: 2012; USEINPARTSLIST: YES; USEWITHLAYOUT: YES; USEWITHSCHEMA: YES; VAL1: 47uF(M); VAL2: 10V
C115-C120 C123-C143 C145-C147 C149-C151 C153-C158 C160-C162 = C: COMP: GDM030000053; COMPONENTNAME: GDM030000053_package; COMPONENTTYPE: 4; FNCLASSCODEG: P03-03; FNPARTSNAMEG: CHIP CERAMIC CAPACITOR (1608); FUNCN: GDM030000053; GCOUNT: 1; MAXGCOUNT: 1; MFFORMINGDIVP: KC; MFMOUNTSYMBOLP: 80; MFPACKAGEMETHOP: S; MFSOLDERINGPROP: .; PCODE: P03B000000MS; SIZECODESMD: 1608; USEINPARTSLIST: YES; USEWITHLAYOUT: YES; USEWITHSCHEMA: YES; VAL1: 22uF(M); VAL2: 6.3V
C121 = C: COMP: G36030011433; COMPONENTNAME: G36030011433_package; COMPONENTTYPE: 4; FNCLASSCODEG: P03-03; FNPARTSNAMEG: CHIP CERAMIC CAPACITOR (1608); FUNCN: G36030011433; GCOUNT: 1; MAXGCOUNT: 1; MFFORMINGDIVP: KC; MFMOUNTSYMBOLP: 80; MFPACKAGEMETHOP: S; MFSOLDERINGPROP: .; PCODE: P03039992230; SIZECODESMD: 1608; USEINPARTSLIST: YES; USEWITHLAYOUT: YES; USEWITHSCHEMA: YES; VAL1: 4.7uF(K); VAL2: 25V
C122 = C: COMP: GDM030000053; COMPONENTNAME: GDM030000053_package; COMPONENTTYPE: 4; FNCLASSCODEG: P03-03; FNPARTSNAMEG: CHIP CERAMIC CAPACITOR (1608); FUNCN: GDM030000053; GCOUNT: 1; MAXGCOUNT: 1; MFFORMINGDIVP: KC; MFMOUNTSYMBOLP: 80; MFPACKAGEMETHOP: S; MFSOLDERINGPROP: .; PCODE: P03B000000MS; SIZECODESMD: 1608; USEINPARTSLIST: YES; USEWITHLAYOUT: YES; USEWITHSCHEMA: YES; VAL1: 10uF(K); VAL2: 25V
C144 C148 C152 C159 C163 = CP: COMP: G36030149044; COMPONENTNAME: G36030149044_package; COMPONENTTYPE: 4; FNCLASSCODEG: P03-02; FNPARTSCODEG: C; FNPARTSNAMEG: POSCAP (TPB); FUNCN: G36030149044; GCOUNT: 1; MAXGCOUNT: 1; MFFORMINGDIVP: KD; MFMOUNTSYMBOLP: 80; MFPACKAGEMETHOP: S; MFSOLDERINGPROP: .; OUMEPARTTYPE: C; PCODE: P03217004212; SIZECODESMD: 7343; USEINPARTSLIST: YES; USEWITHLAYOUT: YES; USEWITHSCHEMA: YES; VAL1: 470uF(M); VAL2: 2V
C164 = CP: COMP: G36030149044; COMPONENTNAME: G36030149044_package; COMPONENTTYPE: 4; FNCLASSCODEG: P03-02; FNPARTSCODEG: C; FNPARTSNAMEG: POSCAP (TPB); FUNCN: G36030149044; GCOUNT: 1; MAXGCOUNT: 1; MFFORMINGDIVP: KD; MFMOUNTSYMBOLP: 80; MFPACKAGEMETHOP: S; MFSOLDERINGPROP: .; NOTMOUNT: NOT MOUNT; OUMEPARTTYPE: C; PCODE: P03217004212; SIZECODESMD: 7343; USEINPARTSLIST: YES; USEWITHLAYOUT: YES; USEWITHSCHEMA: YES
E7 E8 = EB1: COMP: OP-1100; COMPONENTTYPE: 4; VAL1: OP-1100; VAL3: OP-1100
IC9 = LT8609A: COMP: LT8609AHDDM-5#TRPBF; COMPONENTNAME: pinass:LT8609A_func:LT8609A; COMPONENTTYPE: 4; GCOUNT: 1; MAXGCOUNT: 1; OUMEMAKER: Analog Devices; OUMEMAKERKATAMEI: LT8609AHDDM-5#TRPBF; USEINPARTSLIST: YES; USEWITHLAYOUT: YES; USEWITHSCHEMA: YES; VAL1: LT8609AHDDM-5#TRPBF; VAL3: LT8609AHDDM-5#TRPBF
L3 = L: COMP: 74437324100; COMPONENTNAME: L.L; COMPONENTTYPE: 8; GCOUNT: 1; MAXGCOUNT: 1; OUMEMAKER: Wurth Elektronik; OUMEMAKERKATAMEI: 74437324100; USEINPARTSLIST: YES; USEWITHLAYOUT: YES; USEWITHSCHEMA: YES; VAL1: 10uH(M); VAL2: 1.5A; VAL3: 74437324100
L10 = L: COMP: 744774022; COMPONENTNAME: L.L; COMPONENTTYPE: 8; GCOUNT: 1; MAXGCOUNT: 1; OUMEMAKER: Wurth Elektronik; OUMEMAKERKATAMEI: 744774022; USEINPARTSLIST: YES; USEWITHLAYOUT: YES; USEWITHSCHEMA: YES; VAL1: 2.2uH(M); VAL2: 4.6A; VAL3: 744774022
R114 = R: COMP: G36010104216; COMPONENTNAME: G36010104216_package; COMPONENTTYPE: 4; FNCLASSCODEG: P01-08; FNPARTSNAMEG: CHIP RESISTOR (1608); FUNCN: G36010104216; MFFORMINGDIVP: KC; MFMOUNTSYMBOLP: 80; MFPACKAGEMETHOP: S; MFSOLDERINGPROP: .; NOTMOUNT: NOT MOUNT; NUMBEROFELEMENT: 0; PCODE: P01042409226; SIZECODESMD: 1608; TOLERANCE: F; USEINPARTSLIST: YES; USEWITHLAYOUT: YES; USEWITHSCHEMA: YES
R115 = R: COMP: G36010103110; COMPONENTNAME: G36010103110_package; COMPONENTTYPE: 4; FNCLASSCODEG: P01-08; FNPARTSNAMEG: CHIP RESISTOR (1608); FUNCN: G36010103110; MFFORMINGDIVP: KC; MFMOUNTSYMBOLP: 80; MFPACKAGEMETHOP: S; MFSOLDERINGPROP: .; NOTMOUNT: NOT MOUNT; NUMBEROFELEMENT: 0; PCODE: P01042237423; SIZECODESMD: 1608; TOLERANCE: J; USEINPARTSLIST: YES; USEWITHLAYOUT: YES; USEWITHSCHEMA: YES
R116 = R: COMP: G36010027171; COMPONENTNAME: G36010027171_package; COMPONENTTYPE: 4; FNCLASSCODEG: P01-08; FNPARTSNAMEG: CHIP RESISTOR (1608); FUNCN: G36010027171; GCOUNT: 1; MAXGCOUNT: 1; MFFORMINGDIVP: KC; MFMOUNTSYMBOLP: 80; MFPACKAGEMETHOP: S; MFSOLDERINGPROP: .; NUMBEROFELEMENT: 0; PCODE: P01042295621; SIZECODESMD: 1608; TOLERANCE: F; USEINPARTSLIST: YES; USEWITHLAYOUT: YES; USEWITHSCHEMA: YES; VAL1: 33k(F); VAL2: 100mW
R118 = R: COMP: G36010129592; COMPONENTNAME: G36010129592_package; COMPONENTTYPE: 4; FNCLASSCODEG: P01-08; FNPARTSNAMEG: CHIP RESISTOR (1608); FUNCN: G36010129592; GCOUNT: 1; MAXGCOUNT: 1; MFFORMINGDIVP: KC; MFMOUNTSYMBOLP: 80; MFPACKAGEMETHOP: S; MFSOLDERINGPROP: .; NUMBEROFELEMENT: 0; PCODE: P01117063117; SIZECODESMD: 1608; USEINPARTSLIST: YES; USEWITHLAYOUT: YES; USEWITHSCHEMA: YES; VAL1: 27k(D); VAL2: 62.5mW
R119 = R: COMP: G36010014676; COMPONENTNAME: G36010014676_package; COMPONENTTYPE: 4; FNCLASSCODEG: P01-08; FNPARTSNAMEG: CHIP RESISTOR (1608); FUNCN: G36010014676; GCOUNT: 1; MAXGCOUNT: 1; MFFORMINGDIVP: KC; MFMOUNTSYMBOLP: 80; MFPACKAGEMETHOP: S; MFSOLDERINGPROP: .; NUMBEROFELEMENT: 0; PCODE: P01042600623; SIZECODESMD: 1608; USEINPARTSLIST: YES; USEWITHLAYOUT: YES; USEWITHSCHEMA: YES; VAL1: 56k(D); VAL2: 62.5mW
R120 = R: COMP: G36010104254; COMPONENTNAME: G36010104254_package; COMPONENTTYPE: 4; FNCLASSCODEG: P01-08; FNPARTSNAMEG: CHIP RESISTOR (1608); FUNCN: G36010104254; GCOUNT: 1; MAXGCOUNT: 1; MFFORMINGDIVP: KC; MFMOUNTSYMBOLP: 80; MFPACKAGEMETHOP: S; MFSOLDERINGPROP: .; NUMBEROFELEMENT: 0; PCODE: P01042262227; SIZECODESMD: 1608; TOLERANCE: F; USEINPARTSLIST: YES; USEWITHLAYOUT: YES; USEWITHSCHEMA: YES; VAL1: 3.9k(F); VAL2: 100mW
R121 = R: COMP: G36010027034; COMPONENTNAME: G36010027034_package; COMPONENTTYPE: 4; FNCLASSCODEG: P01-08; FNPARTSNAMEG: CHIP RESISTOR (1608); FUNCN: G36010027034; GCOUNT: 1; MAXGCOUNT: 1; MFFORMINGDIVP: KC; MFMOUNTSYMBOLP: 80; MFPACKAGEMETHOP: S; MFSOLDERINGPROP: .; NUMBEROFELEMENT: 0; PCODE: P01042049A26; SIZECODESMD: 1608; TOLERANCE: F; USEINPARTSLIST: YES; USEWITHLAYOUT: YES; USEWITHSCHEMA: YES; VAL1: 10k(F); VAL2: 100mW
S1 = SWMX8: COMP: 219-8LPST; COMPONENTNAME: SWMX8.SWMX8; COMPONENTTYPE: 8; GCOUNT: 1; MAXGCOUNT: 1; OUMEMAKER: CTS; OUMEMAKERKATAMEI: 219-8LPST; USEINPARTSLIST: YES; USEWITHLAYOUT: YES; USEWITHSCHEMA: YES; VAL1: 219-8LPST; VAL3: 219-8LPST
U?#4 = WAKU_DEF100: AUTHOR: q91866sr; COMPONENTTYPE: 2; DATE: 2023/12/25; DRAWINGNUMBER: RD231-SCHEMATIC-01; FUNCTION: 5V Power Supply, VID Switch,Power Output; REVISION: 01; SAVEAREA0: 330961,54,387907,31546; SHEETNUMBER: 4/4; TIME: 19:23:07; TITLE: 48V bus compatible stepdown / DC-DC converter; UPDATEDATE: 2024/01/09; UPDATETIME: 17:47:42; UPDATEUSER: sptcae13

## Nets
VCC5: C63.1 C64.1 C65.1 C66.1 C67.1 C68.1 C87.1 C88.1 C90.1 C91.1 C113.2 C114.2 C121.1 C122.2 IC2.37 IC3.7 IC3.9 IC4.7 IC4.9 IC5.7 IC5.9 IC6.7 IC6.9 IC7.7 IC7.9 L10.2 R27.2 R28.2 R29.2 R34.2 R35.2 R37.1 R38.1 R41.2 R42.2 R43.2 R45.2 R46.2 R106.2 R107.2 R108.2 R109.2 R110.2 R111.2 R112.2 R113.2 R121.2 R122.2
VCC12: C109.1 C110.2 IC9.9 L3.2 R116.1
ISEN1: C48.1 IC2.32 R76.2
ISEN1+: C42.1 IC2.33 R70.2
ISEN2: C50.1 IC2.26 R77.2
ISEN3: C52.1 IC2.35 R78.2
ISEN4: C54.1 IC2.29 R79.2
ISEN5: C56.1 IC2.23 R80.2
LGND: C30.2 C31.2 C32.2 C37.2 C39.2 C40.2 C41.2 C42.2 C43.2 C44.2 C45.2 C46.2 C49.2 C51.2 C53.2 C55.2 C57.2 C60.2 C61.2 C62.2 C63.2 C64.2 C65.2 C66.2 C67.2 C68.2 C72.2 C73.2 C74.2 C75.2 C76.2 C77.2 C78.2 C79.2 C80.2 C81.2 C82.2 C83.2 C84.2 C85.2 C87.2 C88.2 C90.2 C91.2 C96.2 C97.2 C99.2 C100.2 C102.2 C103.2 C105.2 C106.2 C108.1 C109.2 C110.1 C111.1 C114.1 C115.1 C116.1 C117.1 C118.1 C119.1 C120.1 C121.2 C122.1 C123.1 C124.1 C125.1 C126.1 C127.1 C128.1 C129.1 C130.1 C131.1 C132.1 C133.1 C134.1 C135.1 C136.1 C137.1 C138.1 C139.1 C140.1 C141.1 C142.1 C143.1 C144.1 C145.1 C146.1 C147.1 C148.1 C149.1 C150.1 C151.1 C152.1 C153.1 C154.1 C155.1 C156.1 C157.1 C158.1 C159.1 C160.1 C161.1 C162.1 C163.1 C164.1 CN1.2 E8.1 E8.2 E8.3 E8.4 IC2.49 IC3.5 IC3.11 IC4.5 IC4.11 IC5.5 IC5.11 IC6.5 IC6.11 IC7.5 IC7.11 IC9.11 Q6.1 Q6.2 Q6.3 Q8.1 Q8.2 Q8.3 Q10.1 Q10.2 Q10.3 Q11.1 Q11.2 Q11.3 Q12.1 Q12.2 Q12.3 Q13.1 Q13.2 Q13.3 Q15.1 Q15.2 Q15.3 Q17.1 Q17.2 Q17.3 Q20.1 Q20.2 Q20.3 Q21.1 Q21.2 Q21.3 R26.1 R40.1 R44.2 R50.1 R51.1 R56.1 R59.1 R65.1 R66.1 R69.1 R114.1 R115.1 R117.1 R118.1 R119.1 R120.1 R123.1 R124.1 S1.1 S1.2 S1.3 S1.4 S1.5 S1.6 S1.7 S1.8 ; also on sheet 4
PG: C40.1 IC2.40 IC9.8 R67.2 R121.1
PWM1: C61.1 IC2.31 IC3.4
PWM2: C62.1 IC2.25 IC4.4
PWM3: C60.1 IC2.36 IC5.4
PWM4: C84.1 IC2.30 IC6.4
PWM5: C85.1 IC2.24 IC7.4
SIG5: C69.2 IC3.10 L4.1 Q5.1 Q5.2 Q5.3 Q6.5 Q6.6 Q6.7 Q6.8 Q11.5 Q11.6 Q11.7 Q11.8 R76.1
SIG11: IC2.6 R53.2
SIG12: IC2.5 R52.2
SIG13: IC2.4 R63.2
SIG14: IC2.3 R62.2
SIG15: IC2.2 R61.2
SIG16: IC2.1 R60.2
SIG17: Q12.4 R90.2
SIG18: C70.2 IC4.10 L5.1 Q7.1 Q7.2 Q7.3 Q8.5 Q8.6 Q8.7 Q8.8 Q12.5 Q12.6 Q12.7 Q12.8 R77.1
SIG19: Q8.4 R89.2
SIG22: IC4.2 R83.1
SIG23: IC4.6 R89.1 R90.1
SIG24: C70.1 R83.2
SIG26: Q7.4 R88.2
SIG27: IC4.1 R88.1
SIG29: Q13.4 R93.2
SIG30: C71.2 IC5.10 L6.1 Q9.1 Q9.2 Q9.3 Q10.5 Q10.6 Q10.7 Q10.8 Q13.5 Q13.6 Q13.7 Q13.8 R78.1
SIG31: Q10.4 R92.2
SIG34: IC5.2 R84.1
SIG35: IC5.6 R92.1 R93.1
SIG36: C71.1 R84.2
SIG38: Q9.4 R91.2
SIG39: IC5.1 R91.1
SIG41: C94.2 IC7.10 L8.1 Q16.1 Q16.2 Q16.3 Q17.5 Q17.6 Q17.7 Q17.8 Q21.5 Q21.6 Q21.7 Q21.8 R80.1
SIG43: IC7.6 R99.1 R100.1
SIG44: Q20.4 R98.2
SIG46: Q17.4 R99.2
SIG47: C93.2 IC6.10 L7.1 Q14.1 Q14.2 Q14.3 Q15.5 Q15.6 Q15.7 Q15.8 Q20.5 Q20.6 Q20.7 Q20.8 R79.1
SIG48: C94.1 R95.2
SIG49: IC7.2 R95.1
SIG50: Q15.4 R97.2
SIG53: IC6.2 R94.1
SIG54: IC6.6 R97.1 R98.1
SIG55: C93.1 R94.2
SIG57: Q14.4 R101.2
SIG58: IC6.1 R101.1
SIG60: IC7.1 R102.1
SIG61: Q16.4 R102.2
SIG63: Q21.4 R100.2
SIGN6492: C32.1 IC2.21 R29.1
SIGN6507: IC2.17 R57.2
SIGN6515: C37.1 IC2.13 R39.1
SIGN6516: IC2.20 R38.2 R65.2
SIGN6519: IC2.43 R37.2 R40.2
SIGN6523: IC2.10 R34.1 R50.2 R51.2
SIGN6527: C39.1 IC2.48 R45.1 R66.2
SIGN6529: IC2.46 R43.1
SIGN6530: IC2.44 R42.1
SIGN6532: C41.1 IC2.11 R46.1 R68.2
SIGN6534: C31.1 C38.1 IC2.18 R26.2
SIGN6540: IC2.41 R44.1 R67.1
SIGN6715: C43.1 IC2.27 R71.2
SIGN6717: C44.1 IC2.34 R72.2
SIGN6719: C45.1 IC2.28 R73.2
SIGN6721: C46.1 IC2.22 R74.2
SIGN6792: C111.2 IC9.7
SIGN6793: C112.1 IC9.2 L10.1
SIGN6794: C113.1 IC9.6 R114.2 R115.2 R122.1
SIGN6796: C108.2 IC9.3
SIGN6815: IC9.4 R118.2 R119.2
SIGN6816: IC2.42 R58.2
SIGN6820: IC2.45 R28.1
SIGN6828: C112.2 IC9.1
SIGN6838: IC9.5 R117.2
SIGN7001: R35.1 R56.2 R58.1 R59.2
SIGN7098: C36.2 IC2.14 R36.1
SIGN7099: C35.2 C36.1 IC2.15 R33.1 R36.2
SIGN7100: C33.2 C34.1 C35.1 IC2.16 R30.1
SIGN7102: R30.2 R49.2 R57.1
SIGN7103: R31.2 R32.1 R49.1
SIGN7104: C30.1 C38.2 IC2.19 R32.2 R48.2
SIGN7120: IC3.1 R85.1
SIGN7121: Q5.4 R85.2
SIGN7122: Q6.4 R86.2
SIGN7123: IC3.2 R82.1
SIGN7124: C69.1 R82.2
SIGN7125: Q11.4 R87.2
SIGN7126: IC3.6 R86.1 R87.1
SIGN7182: IC9.10 R116.2 R120.2
SIGN7185: IC2.8 R55.2
SIGN7192: IC2.7 R54.2
SIGN7201: IC2.9 R64.2
SIGN7202: CN1.1 R27.1 R64.1
SIGN7206: R68.1 R69.2
VID0: R55.1 R113.1 S1.16
VID1: R54.1 R112.1 S1.15
VID2: R53.1 R111.1 S1.14
VID3: R52.1 R110.1 S1.13
VID4: R63.1 R109.1 S1.12
VID5: R62.1 R108.1 S1.11
VID6: R61.1 R107.1 S1.10
VID7: R60.1 R106.1 S1.9
VP_1R2_VOUT: C48.2 C49.1 C50.2 C51.1 C52.2 C53.1 C54.2 C55.1 C56.2 C57.1 C115.2 C116.2 C117.2 C118.2 C119.2 C120.2 C123.2 C124.2 C125.2 C126.2 C127.2 C128.2 C129.2 C130.2 C131.2 C132.2 C133.2 C134.2 C135.2 C136.2 C137.2 C138.2 C139.2 C140.2 C141.2 C142.2 C143.2 C144.2 C145.2 C146.2 C147.2 C148.2 C149.2 C150.2 C151.2 C152.2 C153.2 C154.2 C155.2 C156.2 C157.2 C158.2 C159.2 C160.2 C161.2 C162.2 C163.2 C164.2 E7.1 E7.2 E7.3 E7.4 L4.2 L5.2 L6.2 L7.2 L8.2 R48.1 R70.1 R71.1 R72.1 R73.1 R74.1 R123.2 R124.2
VP_12V: C72.1 C73.1 C74.1 C75.1 C76.1 C77.1 C78.1 C79.1 C80.1 C81.1 C82.1 C83.1 C96.1 C97.1 C99.1 C100.1 C102.1 C103.1 C105.1 C106.1 L3.1 Q5.5 Q5.6 Q5.7 Q5.8 Q7.5 Q7.6 Q7.7 Q7.8 Q9.5 Q9.6 Q9.7 Q9.8 Q14.5 Q14.6 Q14.7 Q14.8 Q16.5 Q16.6 Q16.7 Q16.8 ; also on sheet 4
N04412: IC2.12 R39.2
N04413: IC2.47 R41.1
N04414: C34.2 R33.2
N04415: C33.1 R31.1

Not connected (* = marked no-connect by the designer): E7 5 6; E8 5 6; IC2 38 39; IC3 3 8; IC4 3 8; IC5 3 8; IC6 3 8; IC7 3 8

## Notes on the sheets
sheet 1
- 2MHz
- +1.2V  0   1   0   0  0   0
- 1
- 0
- X8
- x42
- x5
sheet 2
- x2
- x2
- x2
- x2
- x2
- x2
- x2
- x2
- x2
- x2
- x2
- x2
- x2
- x2
- x2
sheet 3
- PSI
- GND
- 400kHz
